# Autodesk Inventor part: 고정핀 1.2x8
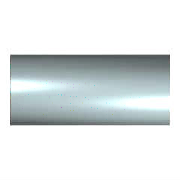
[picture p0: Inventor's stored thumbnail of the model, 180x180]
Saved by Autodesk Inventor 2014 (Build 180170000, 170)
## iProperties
IsCustomPart: 1
Created: 2012-02
Part Number: 고정핀 1.2x8
Material: 강철, 연강
Description: 평행 핀
Document SubType Name: Modeling
Standard: KS B 1320
Designer: P15F
Standards Organization: KS
Language: ko-KR
Size Designation: C 1.2 x  8
Categories: <MemberInstance><Categories><Category DisplayName="조임쇠" InternalName="e4da775c-781d-43d5-af7c-5136215cf5a6" Mnemonic="FSTN"><Category DisplayName="핀" InternalNa
Density: 1 g/cm^3
Appearance: 노란색
Author: P15F
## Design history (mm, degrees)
sketch "스케치1"
  geometry: C1 r 0.6 at (0, 0); 1 further point
  constraints: 1 centre point, 1 coincident
  dimensions: "d1" = 1.2 diameter of C1 (= NND)
extrude "본체" new body sketch "스케치1" distance "d2" = 8 (= NLG); taper "d3" = 0 deg
node "작업 평면1"
sketch "스케치3"
  geometry: 1 further point
body "Solid1"
other parameters: "NND" = 1.2 [user parameter; used in 1 equation term], "NLG" = 8 [user parameter; used in 1 equation term], "d8" = 0, "d9" = 0, "d10" = 0
